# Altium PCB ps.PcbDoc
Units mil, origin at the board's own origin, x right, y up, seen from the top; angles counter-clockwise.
Board outline 5905 x 3540 mil, 2 copper layers (Top Layer, Bottom Layer); 50 components, 20 nets, 112 pads, 0 vias.
Unrouted connection lines stored in the file: 7.
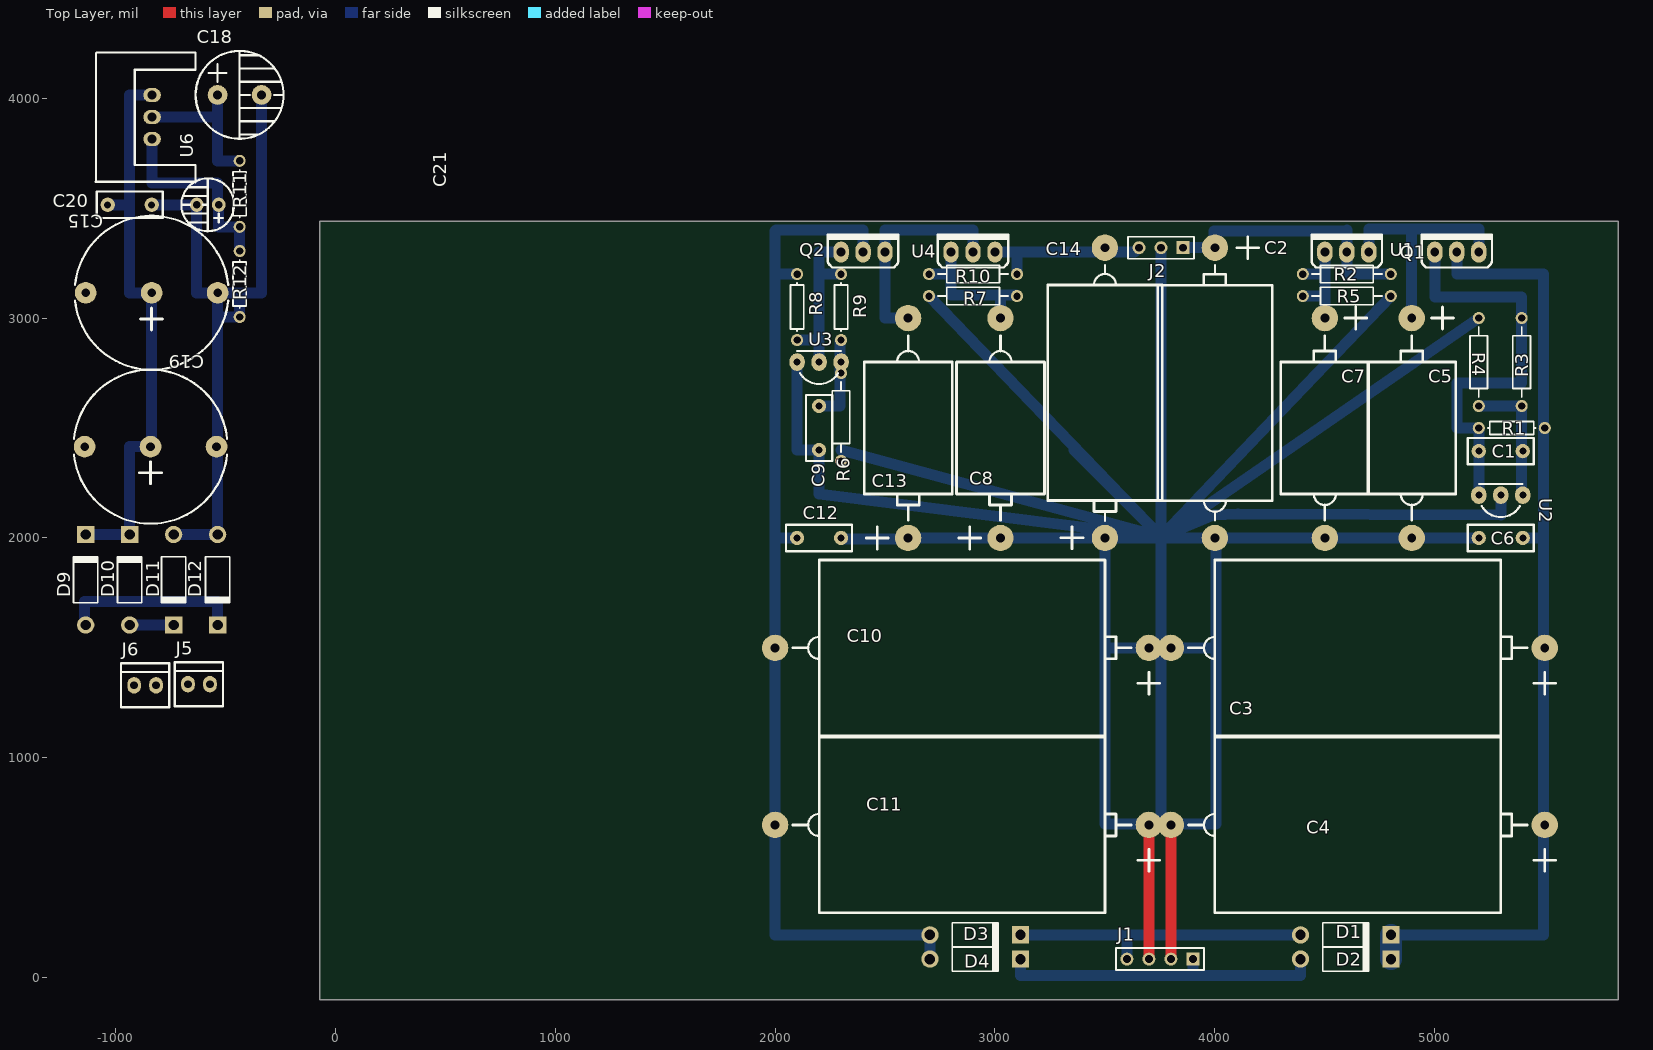
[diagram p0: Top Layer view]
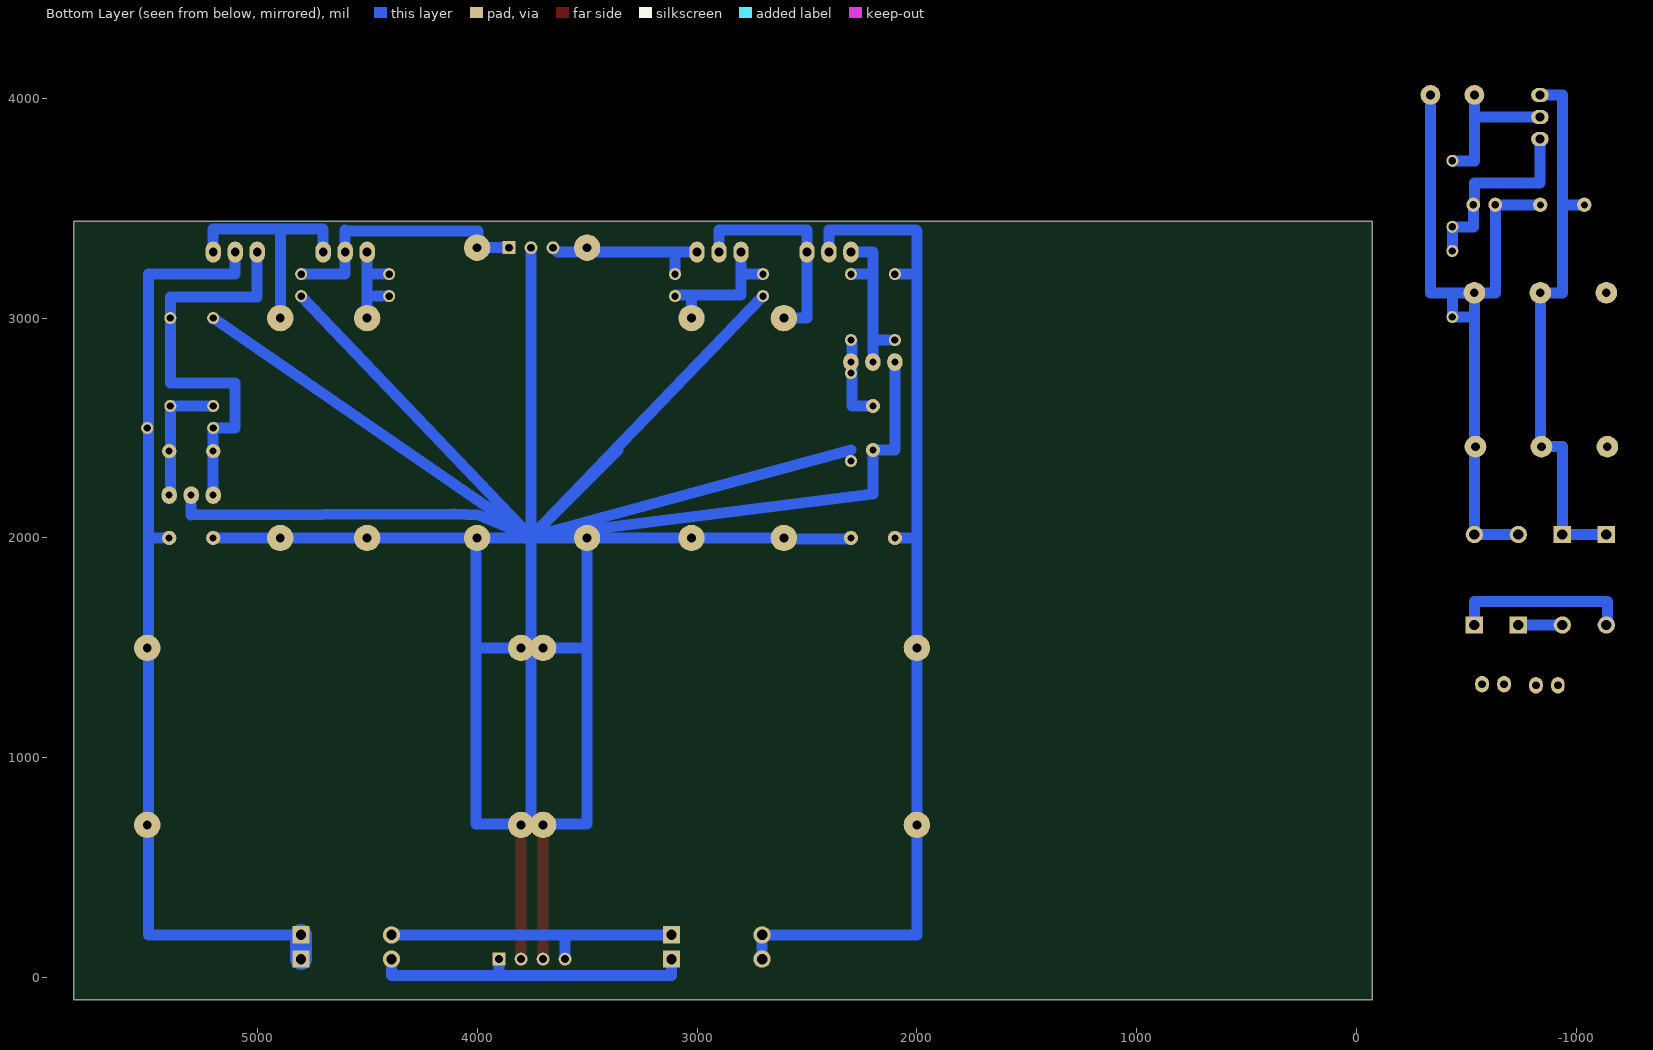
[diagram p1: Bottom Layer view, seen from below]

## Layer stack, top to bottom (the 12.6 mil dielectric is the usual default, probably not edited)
Top Layer: signal copper 1.4
Dielectric: dielectric 12.6, FR-4, Dk 4.8
Bottom Layer: signal copper 1.4

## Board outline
-70,-100 5835,-100 5835,3440 -70,3440

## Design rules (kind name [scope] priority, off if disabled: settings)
Clearance [All] p1: gap=10
ComponentClearance [All] p1 off: gap=10 collisioncheckmode=3 verticalgap=10 showdistances=FALSE
PolygonConnect [All] p1: connectstyle=Relief reliefconductorwidth=10 reliefentries=4 polygonreliefangle="90 Angle"
RoomDefinition PowerSupply [InComponentClass('PowerSupply')] p1 off: confinementstyle=ConfineIn formatcopy=TRUE lockcomponents=FALSE outline 275,30 810,30 810,-385 275,-385
RoutingVias [All] p1: holewidth=28 width=50 viastyle="Through Hole" minholewidth=28 minwidth=50 maxholewidth=28 maxwidth=50
SilkToSilkClearance [All] p1 off: silktosilkclearance=10
SilkscreenOverComponentPads [All] p1 off: minsilkscreentomaskgap=10
SolderMaskExpansion [All] p1: expansion=4
TestPointUsage [All] p1: valid=0 allowmultiple=FALSE
Testpoint [All] p1: side=15 testpointundercomponent=TRUE minsize=40 maxsize=100 preferedsize=60 minholesize=0 maxholesize=40 preferedholesize=32 testpointgrid=1 style=1023 order=0123456789
Width [All] p1: maxlimit=100 minlimit=10 preferedwidth=10 minimp=50.000000 maximp=50.000000 favimp=50.000000
21 further rules are at their usual default settings.

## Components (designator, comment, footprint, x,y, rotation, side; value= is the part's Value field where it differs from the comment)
C1 "104" RAD0.2C 5200,2395 r0 top
C2 "150UF 40V" PEG124_D 4000,3320 r90 top
C3 "40V2200uf" PEG124_J 5500,1500 r0 top
C4 "40V2200uf" PEG124_J 5500,695 r0 top
C5 "10UF 64V" PEG124_A 4895,3000 r90 top
C6 "104" RAD0.2C 5400,2000 r180 top
C7 "10UF 64V" PEG124_A 4500,3000 r90 top
C8 "10UF 64V" PEG124_A 3025,2000 r270 top
C9 "104" RAD0.2C 2200,2600 r270 top
C10 "40V2200uf" PEG124_J 3700,1500 r0 top
C11 "40V2200uf" PEG124_J 3700,695 r0 top
C12 "104" RAD0.2C 2300,2000 r180 top
C13 "10UF 64V" PEG124_A 2605,2000 r270 top
C14 "150UF 40V" PEG124_D 3500,2000 r270 top
C15 "40V1000uf" PEG124_S.7 -835,3115 r180 top
C18 "150UF 40V" RB.2/.4s -535,4015 r0 top
C19 "40V1000uf" PEG124_S.7 -840,2415 r180 top
C20 "104" RAD0.2C -1035,3515 r0 top
C21 "10UF 64V" RB.1/.2C -530,3515 r180 top
D1 "1N4007" DO-41 4595,195 r0 top
D2 "1N4007" DO-41 4595,85 r0 top
D3 "1N4007" DO-41 2910,195 r0 top
D4 "1N4007" DO-41 2910,85 r0 top
D9 "1N4007" DO-41 -1135,1810 r90 top
D10 "1N4007" DO-41 -935,1810 r90 top
D11 "1N4007" DO-41 -535,1810 r270 top
D12 "1N4007" DO-41 -735,1810 r270 top
J1 "Header 4" HDR1X4 3900,85 r180 top
J2 "Header 3" HDR1X3 3855,3320 r180 top
J5 "" SIP2C -670,1335 r90 top
J6 "" SIP2C -915,1330 r90 top
Q1 "2SC5171 TO220" TO-220S 5000,3300 r0 top
Q2 "2SA1930 TO220" TO-220s 2300,3300 r0 top
R1 "1K2" AXIAL-0.3 5350,2500 r0 top
R2 "240R" AXIAL-0.4 4600,3200 r0 top
R3 "33K" AXIAL-0.4 5395,2800 r270 top
R4 "4K7" AXIAL-0.4 5200,2800 r270 top
R5 "3K" AXIAL-0.4 4600,3100 r180 top
R6 "33K" AXIAL-0.4 2300,2550 r270 top
R7 "3K" AXIAL-0.4 2900,3100 r180 top
R8 "1K2" AXIAL-0.3 2100,3050 r270 top
R9 "4K7" AXIAL-0.3 2300,3050 r270 top
R10 "240R" AXIAL-0.4 2900,3200 r180 top
R11 "" AXIAL-0.3 -435,3565 r90 top
R12 "" AXIAL-0.3 -435,3155 r90 top
U1 "LM317" TO-220s 4500,3300 r0 top
U2 "TL431" to-92c 5400,2195 r180 top
U3 "TL431" to-92c 2300,2800 r180 top
U4 "LM337" TO-220s 2800,3300 r0 top
U6 "LM317" TO-220sh -1090,3615 r90 top

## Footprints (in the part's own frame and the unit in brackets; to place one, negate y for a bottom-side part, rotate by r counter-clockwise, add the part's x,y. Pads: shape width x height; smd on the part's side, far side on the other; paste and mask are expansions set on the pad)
AXIAL-0.3 [mm] "Resistor; 2 Leads"
  round 1.4 hole 0.85: 1(-3.81,0) 2(3.81,0)
  silkscreen extent -2.77,-0.76 2.77,0.76
AXIAL-0.4 [mm] "Resistor; 2 Leads"
  round 1.4 hole 0.85: 1(-5.08,0) 2(5.08,0)
  silkscreen extent -4.06,-1.02 4.06,1.02
DO-41 [mm] "Diode, Axial; Body 5.2 x 2.7 mm (LxDia. max), Lead Dia. 0.86 mm (max)"
  round 2 hole 1.2: 1(-5.23,0)
  rect 2x2 hole 1.2: 2(5.23,0)
  silkscreen extent -2.65,-1.4 2.75,1.4
HDR1X3 [mm] "Connector; Header; 3 Position"
  rect 1.5x1.5 hole 0.9: 1(0,0)
  round 1.5 hole 0.9: 2(2.54,0) 3(5.08,0)
  silkscreen extent -1.27,-1.27 6.35,1.27
HDR1X4 [mm] "Connector; Header; 4 Position"
  rect 1.5x1.5 hole 0.9: 1(0,0)
  round 1.5 hole 0.9: 2(2.54,0) 3(5.08,0) 4(7.62,0)
  silkscreen extent -1.27,-1.27 8.89,1.27
PEG124_A [mil]
  round 120 hole 40: 1(0,0) 2(-1000,0)
  silkscreen extent -920,-200 50,200
PEG124_D [mil]
  round 120 hole 40: 1(0,0) 2(-1320,0)
  silkscreen extent -1240,-260 50,260
PEG124_J [mil]
  round 120 hole 40: 1(0,0) 2(-1700,0)
  silkscreen extent -1620,-400 50,400
PEG124_S.7 [mm]
  round 2.5 hole 1: 1(0,0) 2(-7.62,0) 2(7.62,0)
  silkscreen extent -8.84,-8.89 8.84,8.89
RAD0.2C [mil]
  round 65 hole 32: 1(0,0) 2(200,0)
  silkscreen extent -50,-60 250,60
RB.1/.2C [mil]
  oval 62x65 hole 35: 1(0,0) 2(100,0)
  silkscreen extent -70,-120 170,120
RB.2/.4s [mil]
  round 90 hole 40: 1(0,0) 2(200,0)
  silkscreen extent -100,-200 300,200
SIP2C [mil]
  oval 75x62 hole 35: 1(0,0) 2(0,-100)
  silkscreen extent -100,-160 100,60
to-92c [mil]
  oval 70x80 hole 32: 1(0,0) 2(100,0) 3(200,0)
  silkscreen extent 0,-50 200,100
TO-220S [mil]
  oval 70x95 hole 40: 1(0,0) 2(100,0) 3(200,0)
  silkscreen extent -60,-70 260,80
TO-220s [mil]
  oval 70x95 hole 40: 1(0,0) 2(100,0) 3(200,0)
  silkscreen extent -60,-70 260,80
TO-220sh [mil]
  oval 65x80 hole 40: 1(199.06,-256.85) 2(299.06,-256.85) 3(399.06,-256.85)
  silkscreen extent 2,-454 593,-2

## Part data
C1 C6 C9 C12 C20: library part CAP, "Capacitor"
C2 C3 C4 C5 C7 C8 C10 C11 C13 C14 C15 C18 C19 C21: library part ELECTRO1, "Electrolytic Capacitor"
D1 D2 D3 D4 D9 D10 D11 D12: library part "Diode 1N4007", "1 Amp General Purpose Rectifier"
J1: "Header, 4-Pin"
J2: "Header, 3-Pin"
J5 J6: library part "Header 2", "Header, 2-Pin"
Q1: library part NPN, "NPN Transistor"
Q2: library part PNP, "PNP Transistor"
R1 R2 R3 R4 R5 R6 R7 R8 R9 R10 R11 R12: library part Res2, "Resistor"
U1 U6: library part LM217
U4: library part LM137H

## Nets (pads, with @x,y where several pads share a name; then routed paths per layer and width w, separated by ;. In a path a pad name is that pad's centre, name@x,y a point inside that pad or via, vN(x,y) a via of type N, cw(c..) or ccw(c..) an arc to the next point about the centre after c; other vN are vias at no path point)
GND: C2.2 C3.2 C4.2 C5.2 C6.2 C7.2 C8.1 C9.2 C10.1 C11.1 C12.1 C13.1 C14.1 C15.2 C18.2 C19.2 C20.2 C21.2 D11.1 D12.1 J1.2 J1.3 J2.2 J5.2 R4.1 R5.1 R6.2 R7.2 R12.1 U2.2 U3.3 | length 24709.8
  Top Layer w50: J1.3 C11.1 ; J1.2 C4.2
  Bottom Layer w50: C20.2 C21.2 -630,3115 C15.2@-535,3115 ; D12.1 D11.1 C19.2@-535,2415 ; C19.2@-540,2415 C19.2@-535,2415 ; -430,3115 -435,3115 R12.1 -535,3005 -535,3000 ; C18.2 -335,3115 C15.2@-535,3115 ; U3.3 2100,2400 C9.2 2200,2200 3755,2005 ; C12.1@2300,1995 2600,1995 C13.1 C14.1 ; 2300,2400 3755,2005 ; R7.2 3755,2005 ; 3360,2400 3755,2005 ; C11.1 C4.2 3755,740 3755,1610 ; J2.2 3755,2005 ; C3.2 3755,1545 3755,1610 ; 4005,1500 3500,1500 ; C2.2@4005,2000 4005,700 3500,700 3500,1500 ; R5.1 3755,2005 ; C6.2 C7.2 3760,2000 3755,2005 ; R4.1 3755,2005 ; U2.2 5300,2105 4105,2110 3995,2105 3755,2005 ; C19.2@-535,2415 -535,3000 ; -535,3000 C15.2@-535,3115 ; 3500,1500 C14.1 ; C14.1 3750,2000 3755,2005 ; 3755,1610 3755,2005
NetC1_1: C1.1 Q1.1 R1.1 R3.1 U2.3 | length 1895
  Bottom Layer w50: Q1.1 5000,3095 5395,3095 5395,2705 5100,2705 5100,2500 R1.1 U2.3
NetC1_2: C1.2 R3.2 R4.2 U2.1 | length 602.1
  Bottom Layer w50: R4.2 R3.2 5395,2200 U2.1
NetC2_1: C2.1 J2.1 R2.2 U1.2 | length 1229.1
  Bottom Layer w50: J2.1 C2.1 3995,3325 3995,3395 4595,3395 4600,3400 U1.2 4600,3200 R2.2
NetC3_1: C3.1 C4.1 C6.1 D1.2 D2.2 Q1.2 R1.2 | length 4399.1
  Bottom Layer w50: D1.2 5495,195 5495,3200 5200,3200 5100,3200 Q1.2 ; C6.1 5495,2000
  Bottom Layer w100: D2.2 D1.2
NetC5_1: C5.1 Q1.3 U1.3 | length 1122.1
  Bottom Layer w50: U1.3@4705,3295 U1.3 4700,3405 5200,3405 Q1.3 ; C5.1 4895,3405
NetC7_1: C7.1 R2.1 R5.2 U1.1 | length 490
  Bottom Layer w50: R5.2 4495,3100 ; R2.1 4495,3200 ; C7.1 U1.1
NetC8_2: C8.2 R7.1 R10.2 U4.1 | length 709.1
  Bottom Layer w50: R10.2 2795,3200 2800,3195 ; U4.1 2800,3105 3095,3105 R7.1 ; C8.2 3025,3105 3030,3105
NetC9_1: C9.1 R6.1 R9.2 U3.1 | length 397.1
  Bottom Layer w50: C9.1 2295,2600 2295,2895 R9.2
NetC10_2: C10.2 C11.2 C12.2 D3.1 D4.1 Q2.2 R8.1 | length 4718.2
  Bottom Layer w50: 2000,2000 C12.2 ; 2000,3195 2005,3200 R8.1 ; Q2.2 2400,3400 2295,3400 2005,3400 2000,3395 2000,195 D3.1 D4.1
NetC13_2: C13.2 Q2.3 U4.2 | length 1005
  Bottom Layer w50: C13.2 2500,3000 2500,3400 2900,3400 U4.2
NetC14_2: C14.2 J2.3 R10.1 U4.3 | length 763.3
  Bottom Layer w50: U4.3 3635,3300 J2.3 ; R10.1 3100,3300
NetC15_1: C15.1 C19.1 C20.1 D9.2 D10.2 U6.3 | length 2600
  Bottom Layer w50: D9.2 D10.2 -935,2415 C19.1 -835,2415 C15.1 -935,3115 -935,4014.06 U6.3 ; C20.1 -935,3515
NetC18_1: C18.1 J5.1 R11.2 U6.2 | length 698.1
  Bottom Layer w50: U6.2 -535,3914.06 ; C18.1 -535,3914.06 ; R11.2 -535,3715 -535,3914.06
NetC21_1: C21.1 R11.1 R12.2 U6.1 | length 907.2
  Bottom Layer w50: U6.1 -833.15,3615 -535,3615 -535,3515 C21.1 -530,3415 R11.1 R12.2
NetD1_1: D1.1 D3.2 J1.4 | length 1383.2
  Bottom Layer w50: D3.2 D1.1 ; J1.4 3600,195
NetD2_1: D2.1 D4.2 J1.1 | length 1498.2
  Bottom Layer w50: D4.2 3115.91,10 4389.09,10 D2.1 ; 3900,10 J1.1
NetD9_1: D9.1 D11.2 J6.1 | length 821.8
  Bottom Layer w50: D9.1 -1140,1604.09 -1140,1710 -535,1710 D11.2
NetD10_1: D10.1 D12.2 J6.2 | length 200
  Bottom Layer w50: D10.1 D12.2
NetQ2_1: Q2.1 R8.2 R9.1 U3.2 | length 795
  Bottom Layer w50: R8.2 2195,2900 ; U3.2 2200,3300 Q2.1 ; 2200,3200 R9.1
